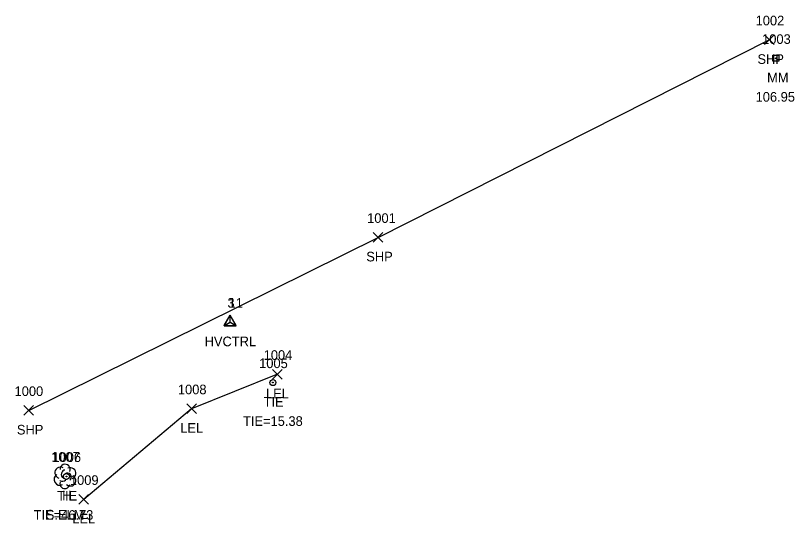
# Model space of a CAD drawing. Extents: x 1483143 to 1488182, y 802902 to 807581.
# Drawn here: x 1484760.6 to 1484922.4, y 802902.2 to 803007.7 of the extents above; entities that cross this region are included whole.
import ezdxf

# ---------------------------------------------------------------- set-up
doc = ezdxf.new("R2010")
doc.units = 0
for name, color, linetype in [('C_A', 7, 'Continuous'), ('C_C', 7, 'Continuous'), ('C_I', 7, 'Continuous'), ('CBP', 7, 'Continuous'), ('CPSM', 7, 'Continuous'), ('L_A', 7, 'Continuous'), ('L_C', 7, 'Continuous'), ('L_I', 7, 'Continuous'), ('L_TIC', 7, 'Continuous'), ('LARO', 7, 'Continuous'), ('LTD', 7, 'Continuous'), ('P_A', 7, 'Continuous'), ('P_I', 7, 'Continuous'), ('P_TIC', 7, 'Continuous'), ('PSP', 7, 'Continuous'), ('S_A', 7, 'Continuous'), ('S_C', 7, 'Continuous'), ('S_I', 7, 'Continuous'), ('SRM', 7, 'Continuous')]:
    doc.layers.add(name, color=color, linetype=linetype)

msp = doc.modelspace()

# ---------------------------------------------------------------- linework, layer by layer
at = {"layer": 'CBP'}
for centre, radius in [((1484814.08, 802931.42), 0.625), ((1484814.08, 802931.42), 0.0833), ((1484771.19, 802911.91), 0.625), ((1484771.19, 802911.91), 0.0833)]:
    msp.add_circle(centre, radius, dxfattribs=at)
at = {"layer": 'CPSM'}
for p, q in [((1484803.96, 802943.25), (1484805.21, 802945.41)), ((1484803.96, 802943.24), (1484805.21, 802945.4)), ((1484806.46, 802943.25), (1484805.21, 802945.41)), ((1484805.21, 802943.97), (1484805.21, 802945.41)), ((1484806.46, 802943.24), (1484805.21, 802945.4)), ((1484805.21, 802943.96), (1484805.21, 802945.4)), ((1484803.96, 802943.25), (1484805.21, 802943.97)), ((1484803.96, 802943.24), (1484805.21, 802943.96)), ((1484805.21, 802943.97), (1484805.21, 802943.97)), ((1484805.21, 802943.97), (1484806.46, 802943.25)), ((1484805.21, 802943.96), (1484805.21, 802943.96)), ((1484805.21, 802943.96), (1484806.46, 802943.24)), ((1484803.96, 802943.25), (1484806.46, 802943.25)), ((1484803.96, 802943.24), (1484806.46, 802943.24))]:
    msp.add_line(p, q, dxfattribs=at)
at = {"layer": 'L_TIC'}
for points in [[(1484814.03, 802932.14), (1484816.03, 802934.14)], [(1484816.03, 802932.14), (1484814.03, 802934.14)], [(1484796.21, 802924.99), (1484798.21, 802926.99)], [(1484798.21, 802924.99), (1484796.21, 802926.99)], [(1484773.78, 802906.16), (1484775.78, 802908.16)], [(1484775.78, 802906.16), (1484773.78, 802908.16)]]:
    msp.add_lwpolyline(points, dxfattribs=at)
at = {"layer": 'LARO'}
msp.add_lwpolyline([(1484815.03, 802933.14), (1484797.21, 802925.99), (1484774.78, 802907.16)], dxfattribs=at)
at = {"layer": 'LTD'}
msp.add_line((1484770.88, 802911.97), (1484770.88, 802911.97), dxfattribs=at)
msp.add_line((1484770.88, 802911.97), (1484770.88, 802911.97), dxfattribs=at)
msp.add_arc((1484770.92, 802913.4), 1.05, 335.5272, 180.9563, dxfattribs=at)
for centre, major_axis, ratio, start_param, end_param in [((1484770.08, 802912.64), (1.21, -0.51), 0.895232, 1.570796, 4.712389), ((1484770.67, 802912.43), (-0.208, -0.792), 0.645439, 3.141593, 6.283185), ((1484771.92, 802912.55), (-1.14, -0.48), 0.949671, 1.570796, 4.712389), ((1484769.79, 802911.26), (0.58, -1.04), 0.959034, 3.141593, 6.283185), ((1484771.38, 802911.8), (-0.5, 0.667), 0.989748, 3.141593, 6.283185), ((1484771.88, 802911.14), (-1.09, 0.79), 0.841452, 1.570796, 4.712389), ((1484770.88, 802910.47), (0.26, 1.06), 0.942809, 1.570796, 4.712389), ((1484770.42, 802911.22), (-0.625, -0.083), 0.423636, 0, 3.141593)]:
    msp.add_ellipse(centre, major_axis=major_axis, ratio=ratio, start_param=start_param, end_param=end_param, dxfattribs=at)
at = {"layer": 'P_TIC'}
for points in [[(1484916.23, 803001.63), (1484918.23, 803003.63)], [(1484918.23, 803001.63), (1484916.23, 803003.63)], [(1484834.95, 802960.59), (1484836.95, 802962.59)], [(1484836.95, 802960.59), (1484834.95, 802962.59)], [(1484762.36, 802924.63), (1484764.36, 802926.63)], [(1484764.36, 802924.63), (1484762.36, 802926.63)]]:
    msp.add_lwpolyline(points, dxfattribs=at)
at = {"layer": 'PSP'}
msp.add_lwpolyline([(1484763.36, 802925.63), (1484835.95, 802961.59), (1484917.23, 803002.63)], dxfattribs=at)
at = {"layer": 'SRM'}
msp.add_lwpolyline([(1484917.96, 802999.41), (1484919.21, 802999.41), (1484919.21, 802998.16), (1484917.96, 802998.16)], close=True, dxfattribs=at)
msp.add_circle((1484918.58, 802998.78), 0.0833, dxfattribs=at)

# ---------------------------------------------------------------- texts
at = {"layer": 'C_A'}
for s, p in [('HVCTRL', (1484799.9, 802938.97)), ('HVCTRL', (1484799.9, 802938.96)), ('TIE', (1484812.16, 802926.42)), ('TIE', (1484769.27, 802906.91))]:
    msp.add_text(s, height=2, dxfattribs=at).set_placement(p)
at = {"layer": 'C_C'}
for s, p in [('TIE=15.38', (1484807.88, 802922.42)), ('TIE=46.73', (1484764.37, 802902.91))]:
    msp.add_text(s, height=2, dxfattribs=at).set_placement(p)
at = {"layer": 'C_I'}
for s, p in [('3', (1484804.64, 802946.97)), ('11', (1484804.88, 802946.96)), ('1005', (1484811.23, 802934.42)), ('1006', (1484768.28, 802914.91))]:
    msp.add_text(s, height=2, dxfattribs=at).set_placement(p)
at = {"layer": 'L_A'}
for s, p in [('LEL', (1484812.66, 802928.14)), ('LEL', (1484794.84, 802920.99)), ('H', (1484770.31, 802906.97)), ('LEL', (1484772.41, 802902.16))]:
    msp.add_text(s, height=2, dxfattribs=at).set_placement(p)
at = {"layer": 'L_C'}
msp.add_text('S.ELM', height=2, dxfattribs=at).set_placement((1484766.91, 802902.97))
at = {"layer": 'L_I'}
for s, p in [('1004', (1484812.17, 802936.14)), ('1008', (1484794.35, 802928.99)), ('1007', (1484768.03, 802914.97)), ('1009', (1484771.92, 802910.16))]:
    msp.add_text(s, height=2, dxfattribs=at).set_placement(p)
at = {"layer": 'P_A'}
for p in [(1484914.77, 802997.63), (1484833.49, 802956.59), (1484760.9, 802920.63)]:
    msp.add_text('SHP', height=2, dxfattribs=at).set_placement(p)
at = {"layer": 'P_I'}
for s, p in [('1002', (1484914.38, 803005.63)), ('1001', (1484833.67, 802964.59)), ('1000', (1484760.42, 802928.63))]:
    msp.add_text(s, height=2, dxfattribs=at).set_placement(p)
at = {"layer": 'S_A'}
msp.add_text('MM', height=2, dxfattribs=at).set_placement((1484916.77, 802993.78))
at = {"layer": 'S_C'}
msp.add_text('106.95', height=2, dxfattribs=at).set_placement((1484914.38, 802989.78))
at = {"layer": 'S_I'}
msp.add_text('1003', height=2, dxfattribs=at).set_placement((1484915.73, 803001.78))

doc.saveas('drawing.dxf')
